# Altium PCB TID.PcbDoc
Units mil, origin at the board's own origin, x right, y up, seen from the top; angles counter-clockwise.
Board outline 3000 x 3000 mil, 2 copper layers (Top Layer, Bottom Layer), stack 60.8 mil thick; 40 components, 14 nets, 74 pads, 172 vias.
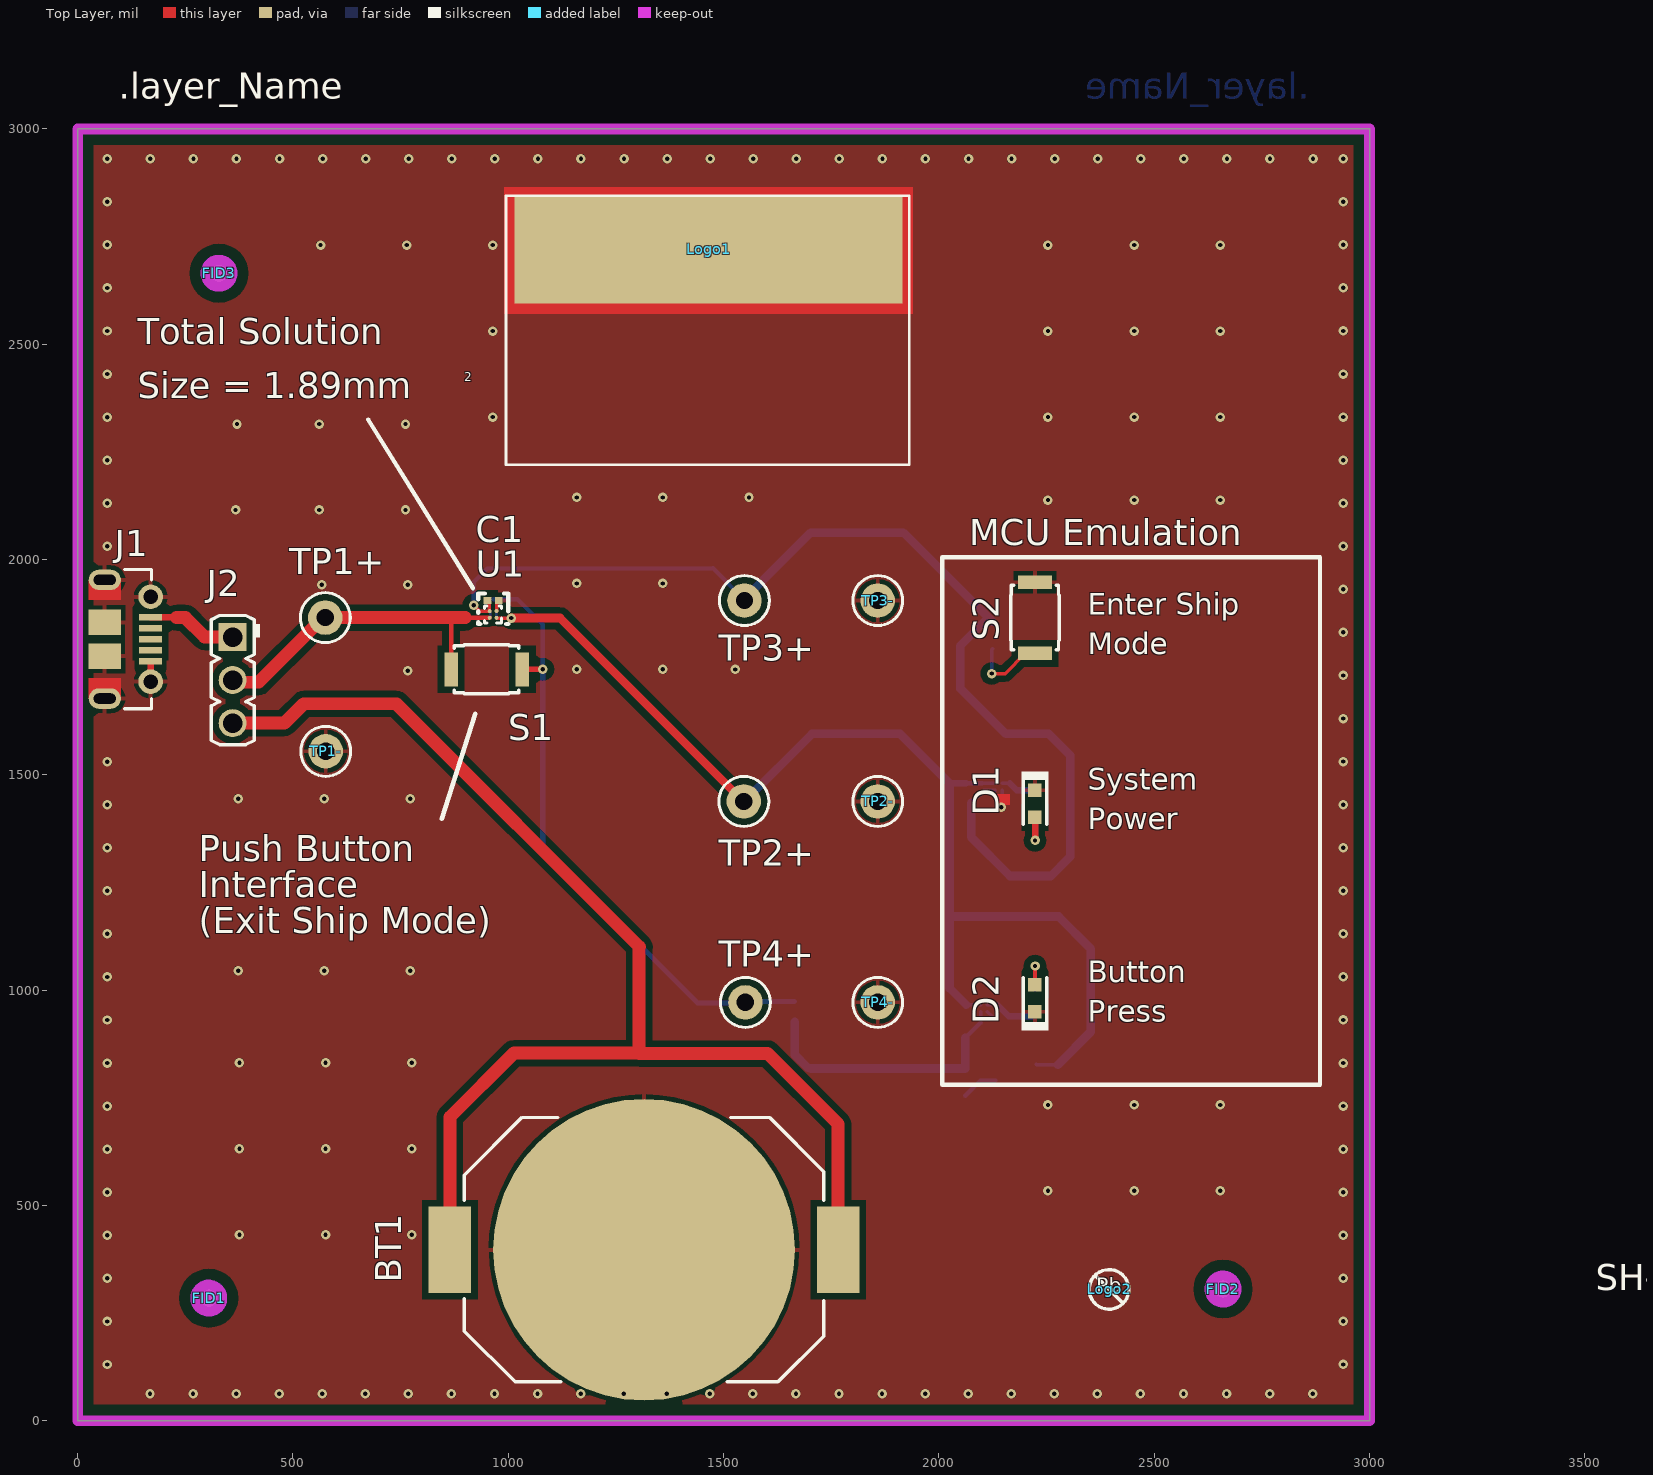
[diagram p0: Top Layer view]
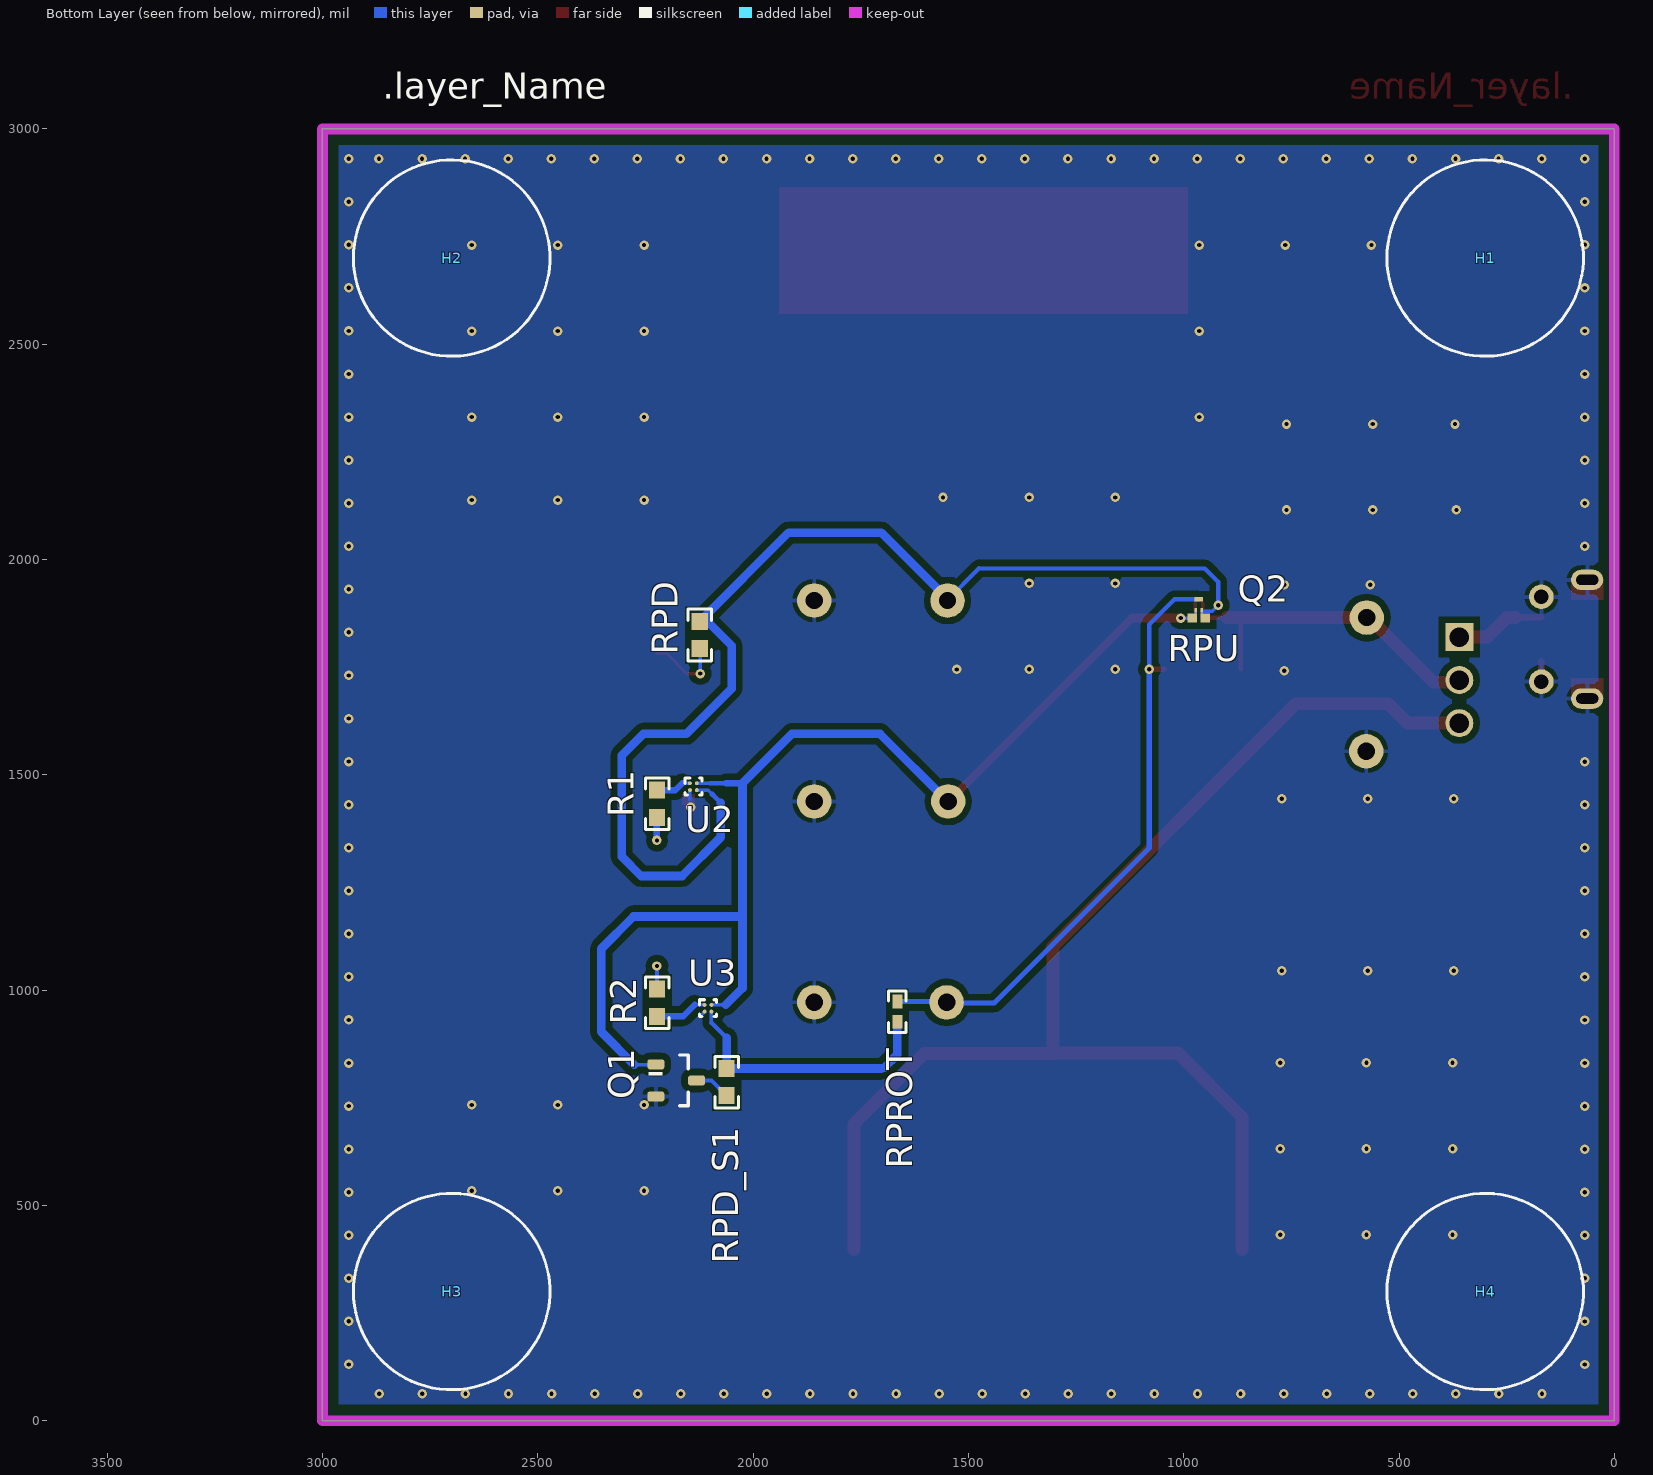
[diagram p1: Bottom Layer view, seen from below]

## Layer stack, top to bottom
Top Solder: solder mask 0.4, Solder Resist, Dk 3.5
Top Layer: signal copper 1.4
Dielectric1: core 58, FR-4, Dk 4.8
Bottom Layer: signal copper 1.4
Bottom Solder: solder mask 0.4, Solder Resist, Dk 3.5

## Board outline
0,0 3000,0 3000,3000 0,3000

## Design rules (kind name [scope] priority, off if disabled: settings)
AcuteAngle [All] p1: minimum=4.50000000000000E+0001 checktracksonly=FALSE
AssemblyTestPointUsage [All] p1: valid=2
Clearance Clearance_RPU2 [InComponent('RPU2')] p1: gap=5
Clearance "Clearance_J1 to Keep out" [HasFootprint('CONN_105017-0001') vs IsKeepOut] p2: gap=10
Clearance Clearance_track [IsTrack vs IsTrack] p3: gap=6
Clearance "Clearance_U1,U2 and U3" [InComponent('U*')] p4: gap=6
Clearance Clearance_Keepouts [((IsTrack Or IsArc) And Not InPoly) And IsFree and IsKeepOut vs ((IsTrack Or IsArc) And Not InPoly) And IsFree and IsKeepOut] p5: gap=0
Clearance Clearance_BoardEdge_MountingHoles [OnCopper and InComponentClass('Mounting Holes') vs IsKeepOut] p6: gap=25
Clearance Clearance_BoardEdge_Poly [OnCopper and InPoly vs IsKeepOut] p7: gap=25
Clearance Clearance_BoardEdge [OnCopper and Not InComponentClass('Logo') and not InComponentClass('FiducialMark') and not InRegion(1000,500,4000,800) and Not IsKeepout vs IsKeepOut] p8: gap=25
Clearance Clearance_Poly [InPolygon] p9: gap=15
Clearance [All] p10: gap=7.87
ComponentClearance ComponentClearance_MountingHoles_FiducialMarks [InComponentClass('Mounting Holes') vs InComponentClass('FiducialMark')] p1 off: gap=50 collisioncheckmode=3 verticalgap=10 showdistances=FALSE
ComponentClearance ComponentClearance_Shunt [InComponentClass('Header') vs InComponentClass('Shunt')] p2 off: gap=0 collisioncheckmode=3 verticalgap=0 showdistances=FALSE
ComponentClearance ComponentClearance_Logo [InComponentClass('Logo')] p3 off: gap=50 collisioncheckmode=3 verticalgap=10 showdistances=FALSE
ComponentClearance ComponentClearance_ScrewToNut [(HasFootprint('NY PMS 440 0025 PH')) vs (HasFootprint('Keystone_1902C'))] p4 off: gap=5 collisioncheckmode=3 verticalgap=10 showdistances=FALSE
ComponentClearance ComponentClearance_MountingHoles [InComponentClass('Mounting Holes')] p5 off: gap=250 collisioncheckmode=3 verticalgap=100000 showdistances=FALSE
ComponentClearance ComponentClearance_SmallPassives [HasFootprint('0201*') or HasFootprint('0402*') or HasFootprint('0508') or HasFootprint('0603*') or HasFootprint('0612') or HasFootprint('0805*') or HasFootprint('0815*') or HasFootprint('0830*') or HasFootprint('1206*') or HasFootprint('1210*') or HasFootprint('1808*') or HasFootprint('1812*') or HasFootprint('1825*') or HasFootprint('2010*') or HasFootprint('2220*') or HasFootprint('2225*') or HasFootprint('2512*') or HasFootprint('2728*') or HasFootprint('3518*') vs HasFootprint('0201*') or HasFootprint('0402*') or HasFootprint('0508') or HasFootprint('0603*') or HasFootprint('0612') or HasFootprint('0805*') or HasFootprint('0815*') or HasFootprint('0830*') or HasFootprint('1206*') or HasFootprint('1210*') or HasFootprint('1808*') or HasFootprint('1812*') or HasFootprint('1825*') or HasFootprint('2010*') or HasFootprint('2220*') or HasFootprint('2225*') or HasFootprint('2512*') or HasFootprint('2728*') or HasFootprint('3518*')] p6 off: gap=20 collisioncheckmode=3 verticalgap=10 showdistances=FALSE
ComponentClearance ComponentClearance_THtoSMT [IsThruComponent vs IsSMTComponent] p7 off: gap=100 collisioncheckmode=3 verticalgap=30 showdistances=FALSE
ComponentClearance ComponentClearance_THtoTH [IsThruComponent vs IsThruComponent] p8 off: gap=118.11 collisioncheckmode=3 verticalgap=30 showdistances=FALSE
ComponentClearance [All] p9 off: gap=40 collisioncheckmode=3 verticalgap=10 showdistances=FALSE
DiffPairsRouting [All] p1: maxlimit=100 minlimit=10 mostfreqgap=10 toplayer_minwidth=15 toplayer_maxwidth=15 toplayer_prefwidth=15 bottomlayer_minwidth=15 bottomlayer_maxwidth=15 bottomlayer_prefwidth=15 maxuncoupledlength=1000
FabricationTestPointUsage TestPointUsage [All] p1: valid=2 allowmultiple=FALSE
FabricationTestpoint Testpoint [All] p1: side=3 testpointundercomponent=TRUE minsize=40 maxsize=100 preferedsize=60 minholesize=0 maxholesize=40 preferedholesize=32 testpointgrid=1 allowsidetop=TRUE allowsidebottom=TRUE usegrid=TRUE gridtolerance=0.01
FanoutControl Fanout_LCC [IsLCC] p1: bgadir=Out bgaviamode=Centered fanoutstyle=Auto fanoutdirection=Alternating viagrid=1 // Fanout_LCC (Default Rule)
FanoutControl Fanout_BGA [IsBGA] p2: bgadir=Out bgaviamode=Centered fanoutstyle=Auto fanoutdirection=Alternating viagrid=1 // Fanout_BGA (Default Rule)
FanoutControl Fanout_Default [All] p4: bgadir=Out bgaviamode=Centered fanoutstyle=Auto fanoutdirection=Alternating viagrid=1 // Fanout_Default (Default Rule)
FanoutControl Fanout_Small [(CompPinCount < 5)] p5: bgadir=Out bgaviamode=Centered fanoutstyle=Auto fanoutdirection=OutThenIn viagrid=1 // Fanout_Small (Default Rule)
Height [All] p1 off: minheight=0 maxheight=1000 prefheight=500
HoleSize [All] p1: absolutevalues=TRUE maxlimit=251 minlimit=8 maxpercent=80.000 minpercent=20.000
MinimumAnnularRing MinimumAnnularRing_ThermalPadVias [IsVia and InAnyComponent] p1: minimumring=5.91
MinimumAnnularRing [All] p2: minimumring=6
MinimumSolderMaskSliver MinimumSolderMaskSliver_Logo [InComponentClass('Logo') vs InComponentClass('Logo')] p1: minsoldermaskwidth=0.7
MinimumSolderMaskSliver [All] p2: minsoldermaskwidth=3.94
PlaneClearance PlaneClearance_1 [All] p1: clearance=20
PlaneClearance [InNet('NetJ2_2')] p2: clearance=0
PlaneConnect [All] p1: planeconnectstyle=Relief reliefexpansion=10 reliefentries=4 reliefconductorwidth=10 reliefairgap=10
PolygonConnect [(InPadClass('All Pads'))] p1: connectstyle=Relief reliefconductorwidth=10 reliefentries=4 polygonreliefangle="90 Angle" airgapwidth=10
RoutingVias ThermalPadVias [IsVia and InAnyComponent] p1: holewidth=7.87 width=19.68 viastyle="Through Hole" minholewidth=7.87 minwidth=19.68 maxholewidth=12.99 maxwidth=23.62
RoutingVias [All] p2: holewidth=16 width=34 viastyle="Through Hole" minholewidth=7.87 minwidth=22 maxholewidth=40 maxwidth=65
SilkToBoardRegionClearance [Not ((IsComment or IsDesignator) And (Hide <> 'False')) and not InRegion(1000,500,4000,800)] p1:
SilkToSilkClearance SilkToSilkClearance_Pb-FreeLogo [(HasFootprint('Pb-Free_Overlay_Medium') OR HasFootprint('Pb-Free_Overlay_Small')) vs (HasFootprint('Pb-Free_Overlay_Medium') OR HasFootprint('Pb-Free_Overlay_Small'))] p1: silktosilkclearance=0
SilkToSilkClearance [All] p2: silktosilkclearance=5
SilkToSolderMaskClearance "Silk to Solder Mask Opening" [All] p1: minsilkscreentomaskgap=1 clearancetoexposedcopper=FALSE
SolderMaskExpansion [All] p1: expansion=1.97
UnpouredPolygon [All] p1: allowunpoured=FALSE
Width [All] p1: maxlimit=100 minlimit=6 preferedwidth=10 checkconnectedcopper=TRUE
12 further rules are at their usual default settings.

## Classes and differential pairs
component class Ship_Mode_Circuit: BT1 C1 D1 D2 J1 J2 Q1 Q2 R1 R2 RPD RPD_S1 RPROT RPU S1 S2 SH-J2 TP1+ TP1- TP2+ TP2- TP3+ TP3- TP4+ TP4- U1 U2 U3
component class Logo: Logo1
component class TID_Hardware: FID1 FID2 FID3 H1 H2 H3 H4 Logo1 Logo2 ZZ2 ZZ3 ZZ4
component class FiducialMark: FID1 FID2 FID3
component class AssemblyNote: ZZ2 ZZ3 ZZ4
component class Header: J2
component class Shunt: SH-J2

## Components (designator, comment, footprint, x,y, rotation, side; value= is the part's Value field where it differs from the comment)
BT1 "BAT-HLD-001" LINX_BAT-HLD-001 1315.3,397.2 r180 top
C1 "CL03A105MP3NSNC" 0201 965,1905 r0 top
D1 "Power Active" WL-SMCW_GREEN 2223.07,1432.7 r270 top
D2 "Button Active" WL-SMCW_GREEN 2223.07,981.2 r90 top
FID1 "Fiducial" Fiducial10-20 304.5,284.7 r0 top
FID2 "Fiducial" Fiducial10-20 2659.7,305.8 r0 top
FID3 "Fiducial" Fiducial10-20 328.2,2664.7 r0 top
H1 "SJ-5303 (CLEAR)" Bumpon_SJ5003Transparent 300,2700 r180 bottom
H2 "SJ-5303 (CLEAR)" Bumpon_SJ5003Transparent 2700,2700 r180 bottom
H3 "SJ-5303 (CLEAR)" Bumpon_SJ5003Transparent 2700,300 r180 bottom
H4 "SJ-5303 (CLEAR)" Bumpon_SJ5003Transparent 300,300 r180 bottom
J1 "105017-0001" CONN_105017-0001 116.2,1814.8 r270 top
J2 "61300311121" WURTH_61300311121 360,1720 r270 top
Logo1 "Texas Instruments" TI_Stacked_SolderMask_Small 1465,2720 r0 top
Logo2 "Pb-Free Symbol" Pb-Free_Overlay_Small 2395,305 r0 top
Q1 "BSS123" SOT-23 2178.56,790.2 r180 bottom
Q2 "CSD23382F4" YJC0003A 965,1895 r180 bottom
R1 "CRCW0603220RJNEA" 0603 2223.1,1432.7 r270 bottom
R2 "CRCW0603220RJNEA" 0603 2223.03,970.7 r90 bottom
RPD "CRCW0603100RJNEA" 0603 2123.96,1824.54 r90 bottom
RPD_S1 "RC1608J103CS" 0603 2061.36,786.4 r90 bottom
RPROT "CRCW04021K00JNED" 0402 1665,950 r270 bottom
RPU "RC0603F202CS" 0201M 965,1864 r0 bottom
S1 "Exit Ship Mode" SW_SKRKAEE010 950,1745 r180 top
S2 "Enter Ship Mode" SW_SKRKAEE010 2223.07,1864.54 r90 top
SH-J2 "969102-0000-DA" SNT-100-BK-G 3568,171 r90 top
TP1+ "5000" Keystone5000 575,1865 r90 top
TP1- "5001" Keystone5001 576.1,1554.6 r90 top
TP2+ "5000" Keystone5000 1546.9,1438.15 r90 top
TP2- "5001" Keystone5001 1858,1438.15 r90 top
TP3+ "5004" Keystone5004 1548.4,1904.7 r90 top
TP3- "5001" Keystone5001 1858,1904.7 r90 top
TP4+ "5004" Keystone5004 1550.5,971.6 r90 top
TP4- "5001" Keystone5001 1858,971.6 r90 top
U1 "TPS22915BYFP" YFP0004AAAA 964.7,1872.4 r180 top
U2 "TPS22915BYFP" YFP0004AAAA 2138.73,1472.4 r180 bottom
U3 "TPS22915BYFP" YFP0004AAAA 2104.7,957.9 r180 bottom
ZZ2 "These assemblies are ESD sensitive, ESD precautions shall be observed." AssemblyNote 5,3845 r0 top
ZZ3 "These assemblies must be clean and free from flux and all contaminants. Use of no clean flux is not acceptable." AssemblyNote 5,3577.5 r0 top
ZZ4 "These assemblies must comply with workmanship standards IPC-A-610 Class 2, unless otherwise specified." AssemblyNote 5,3310 r0 top

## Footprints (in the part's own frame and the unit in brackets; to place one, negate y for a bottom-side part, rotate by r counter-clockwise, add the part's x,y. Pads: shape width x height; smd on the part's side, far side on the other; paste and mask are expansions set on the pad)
0201 [mm] "Data from Kemet datasheet CC101_COM dated 7/28/11"
  rect 0.46x0.42 smd mask+0.048: 1(-0.33,0) 2(0.33,0)
  body extent -0.31,-0.16 0.31,0.16, height 0.26
0201M [mm] "Data from Kemet datasheet CC101_COM dated 7/28/11"
  rect 0.56x0.52 smd mask+0.048: 1(-0.38,0) 2(0.38,0)
  body extent -0.31,-0.16 0.31,0.16, height 0.26
0402 [mm] "0402 from SM-752 data"
  rect 0.8x0.6 smd: 1(-0.6,0) 2(0.6,0)
  silkscreen extent -1.22,-0.52 1.22,0.52, body extent -0.55,-0.3 0.55,0.3, height 0.6
0603 [mm] "0603 from SM-752 data"
  rect 1x0.95 smd: 1(-0.8,0) 2(0.8,0)
  silkscreen extent -1.52,-0.69 1.52,0.69, body extent -0.87,-0.47 0.87,0.47, height 0.85
AssemblyNote [mil] "Assembly Note"
Bumpon_SJ5003Transparent [mil] "3M Hemispherical Bumpon transparent"
  round 1 on Mech4: 0(0,0)
  silkscreen extent -228,-228 228,228, body extent -217,-218 219,218, height 197
CONN_105017-0001 [mm] "Molex Micro USB-B"
  rect 0.4x1.35 smd mask+0.051: 1(-1.3,1.35) 2(-0.65,1.35) 3(0,1.35) 4(0.65,1.35) 5(1.3,1.35)
  oval 1.2x1.9 hole 0.6 slot 1.3 at 90 deg: 6(-3.5,-1.35) 9(3.5,-1.35)
  rect 1.5x1.9 smd: 7(-1,-1.35) 8(1,-1.35)
  round 1.45 hole 0.85: 10(2.5,1.35) 11(-2.5,1.35)
  Top Layer region: 3.5,-0.4 2.3,-0.4 2.3,-2.3 3.5,-2.3
  Top Layer region: -3.5,-2.3 -2.3,-2.3 -2.3,-0.4 -3.5,-0.4
  silkscreen extent -4.1,-0.2 4.1,1.4, body extent -4.1,-3.93 4.1,1.5, height 2.72
Fiducial10-20 [mm]
  round 1 smd mask+0.5: 1(0,0)
  Top Layer keep-out circle w1.178: c0,0 r0.5
Keystone5000 [mil] "For Keystone 500x miniature loop terminals"
  round 80 hole 40: 1(0,0)
  silkscreen extent -58,-58 58,58, body extent -49,-49 49,49, height 182
Keystone5001 [mil] "For Keystone 500x miniature loop terminals"
  round 80 hole 40: 1(0,0)
  silkscreen extent -58,-58 58,58, body extent -49,-49 49,49, height 182
Keystone5004 [mil] "For Keystone 500x miniature loop terminals"
  round 80 hole 40: 1(0,0)
  silkscreen extent -58,-58 58,58, body extent -49,-49 49,49, height 182
LINX_BAT-HLD-001 [mm] "Linx Technologies"
  round 17.8 smd: 1(0,0)
  rect 2.5x5.1 smd: 2(-11.45,0) 3(11.45,0)
  silkscreen extent -10.6,-7.8 10.6,7.8, body extent -10.6,-7.8 10.6,7.8, height 4.31
Pb-Free_Overlay_Small [mil]
  silkscreen extent -46,-46 46,46
SNT-100-BK-G [mil] "Samtec STEP model"
  round 1 on Mech3: 0(0,0)
  body extent -100,-50 100,50, height 344
SOT-23 [mm] "SOT23, 3-Leads, Body 2.9x1.3mm, Pitch 0.95mm, Lead Span 2.5mm, IPC Medium Density"
  rrect50% 1x0.6 smd: 1(-1.2,0.95) 2(-1.2,-0.95) 3(1.2,0)
  silkscreen extent -1.63,-1.5 0.7,1.5, body extent -1.16,-1.45 1.21,1.45, height 1
SW_SKRKAEE010 [mm] "Alps recommended land pattern"
  rect 0.8x2 smd: 1(-2.1,0) 2(2.1,0)
  silkscreen extent -1.9,-1.44 1.92,1.44, body extent -2.4,-1.45 2.4,1.45, height 1.96
TI_Stacked_SolderMask_Small [mil]
  rect 900x250 smd paste-125 mask-125: 0(0,0)
WL-SMCW_GREEN [mm] "WURTH"
  rect 0.8x0.8 smd: 1(-0.8,0) 2(0.8,0)
  silkscreen extent -1.9,-0.8 1.2,0.8, body extent -0.85,-0.45 0.85,0.45, height 0.8
WURTH_61300311121 [mm] "Header, 2.54mm, 3x1, TH"
  rect 1.65x1.65 hole 1.15: 1(-2.54,0)
  round 1.65 hole 1.15: 2(0,0) 3(2.54,0)
  silkscreen extent -3.81,-1.27 3.81,1.6, body extent -3.81,-1.27 3.81,1.27, height 8.54
YFP0004AAAA [mm] "TI DSBGA 0.806x0.806mm"
  round 0.23 smd paste-0.13 mask+0: A1(-0.2,0.2) A2(0.2,0.2) B1(-0.2,-0.2) B2(0.2,-0.2)
  silkscreen extent -0.5,-0.5 0.5,0.5, body extent -0.39,-0.39 0.39,0.39, height 0.5
YJC0003A [mm] "TI"
  rect 0.16x0.26 smd: 1(-0.175,-0.325) 2(0.175,-0.325)
  rect 0.51x0.26 smd: 3(0,0.325)
  body extent -0.32,-0.52 0.32,0.52, height 0.35

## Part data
BT1: "Battery Holder, Retainer clip, SMT"
C1: "CAP, CERM, 1 µF, 10 V, +/- 20%, X5R, 0201"
D1 D2: library part 150060VS75000, "LED, Green, SMD"
FID1 FID2 FID3: "Fiducial mark.  There is nothing to buy or mount."
H1 H2 H3 H4: "Bumpon, Hemisphere, 0.44 X 0.20, Clear"
J1: "Connector, Receptacle, Micro-USB Type B, R/A, Bottom Mount SMT"
J2: "Header, 2.54 mm, 3x1, Gold, TH"
Logo1: library part TI_Logo, "Texas Instrument Corporate Signature"
Logo2: library part Pb-Free
Q1: "MOSFET, N-CH, 100 V, 0.17 A, SOT-23"
Q2: library part CSD23381F4, "MOSFET, P-CH, -12 V, -3.5 A,"
R1 R2: "RES, 220, 5%, 0.1 W, 0603"
RPD: "RES, 100, 5%, 0.1 W, 0603"
RPD_S1: "RES, 10 k, 5%, 0.1 W, 0603"
RPROT: "RES, 1.0 k, 5%, 0.063 W, 0402"
RPU: library part CRCW02011K80FKED, "RES, 2 k, 1%, 0.05 W, 0201"
S1 S2: library part SKRKAEE010, "Switch, Push Button, SMD"
SH-J2: "Shunt, 100mil, Gold plated, Black"
TP1+ TP2+: "Test Point, Miniature, Red, TH"
TP1- TP2- TP3- TP4-: "Test Point, Miniature, Black, TH"
TP3+ TP4+: "Test Point, Miniature, Yellow, TH"
U1 U2 U3: "Single Channel Ultra-Low Resistnace Load Switch, YFP0004AAAA"
ZZ2 ZZ3 ZZ4: library part AssemblyNote

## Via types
v1: diameter 22, hole 10, Top Layer to Bottom Layer, tented both sides, 172 vias

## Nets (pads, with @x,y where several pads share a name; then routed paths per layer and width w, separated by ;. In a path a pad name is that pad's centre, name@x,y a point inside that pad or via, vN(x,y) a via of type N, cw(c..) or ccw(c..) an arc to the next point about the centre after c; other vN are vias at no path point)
"BUTTON INDICATOR": RPD_S1.2 RPROT.2 U3.B2 | length 624.9
  Bottom Layer w8: 2096.83,924.23 U3.B2
  Bottom Layer w10: 2061.36,888.76 2096.83,924.23
  Bottom Layer w20: RPROT.2 1665,850 1695,820 ; 1702.11,817.89 RPD_S1.2 2061.36,888.76
DRAIN: Q2.3 RPROT.1 S1.1 TP4+.1 | length 1432
  Top Layer w12: S1.1@1045,1745 v1(1080,1745)
  Bottom Layer w10: Q2.3 1021.2,1907.8 1080,1849 v1(1080,1745)
  Bottom Layer w12: v1(1080,1745) 1080,1330 1440,970 TP4+.1@1555,970 ; TP4+.1@1550.5,973.62 RPROT.1
GATE: Q1.1 Q2.1 RPU.2 TP2+.1 U1.A1 U2.A2 U3.A2 | length 2763
  Top Layer w8: U1.A1@973,1865 974,1864 v1(1007,1864)
  Top Layer w20: v1(1007,1864) 1120,1864 TP2+.1@1546,1438
  Bottom Layer w6: RPU.2@971.89,1868.11 Q2.1
  Bottom Layer w8: RPU.2@981,1864 v1(1007,1864) ; 2063.1,966.4 2063.73,965.77 U3.A2 ; 2100.27,1480.27 U2.A2 ; Q1.1 2226.6,826.8 2276.4,826.8
  Bottom Layer w10: 2062.9,1480.27 2100.27,1480.27
  Bottom Layer w15: 2024.6,1478.57 2022.9,1480.27 2062.9,1480.27
  Bottom Layer w20: TP2+.1 1548.15,1438.15 1705,1595 1910,1595 2022.9,1482.1 2022.9,1480.27 ; 2024.6,1171 2277.8,1171 2352.7,1096.1 2352.7,903.1 2276.4,826.8 ; 2024.6,1478.57 2024.6,1004.9 2063.1,966.4
GND: BT1.1 C1.2 D1.1 D2.1 J1.5 J1.6 J1.7 J1.8 J1.9 J1.10 J1.11 Q1.2 S2.2 TP1-.1 TP2-.1 TP3-.1 TP4-.1 U1.B1 U2.B1 U3.B1 | length 101.7
  Top Layer w8: U1.B1 972.94,1880.64 C1.2@972.94,1897.94
  Top Layer w15: J1.10 J1.5
  Bottom Layer w8: U3.B1 2123.4,939.2 ; 2146.61,1443.19 U2.B1
  other v1: 168,62.4 268,62.4 368,62.4 468,62.4 568,62.4 668,62.4 768,62.4 868,62.4 968,62.4 1068,62.4 1168,62.4 1268,62.4 1368,62.4 1468,62.4 1568,62.4 1668,62.4 1768,62.4 1868,62.4 1968,62.4 2068,62.4 2168,62.4 2268,62.4 2368,62.4 2468,62.4 2568,62.4 2668,62.4 2768,62.4 2868,62.4 68.8,130.6 2939.2,130.7 68.8,230.6 2939.2,230.7 68.8,330.6 2939.2,330.7 68.8,430.6 2939.2,430.7 375.6,432.2 575.6,432.2 775.6,432.2 68.8,530.6 2939.2,530.7 2253.3,533.8 2453.3,533.8 2653.3,533.8 68.8,630.6 2939.2,630.7 375.6,631.8 575.6,631.8 775.6,631.8 68.8,730.6 2939.2,730.7 2253.3,733.4 2453.3,733.4 2653.3,733.4 68.8,830.6 2939.2,830.7 375.6,831.5 575.6,831.5 775.6,831.5 68.8,930.6 2939.2,930.7 68.8,1030.6 2939.2,1030.7 372.6,1045.1 572.6,1045.1 772.6,1045.1 68.8,1130.6 2939.2,1130.7 68.8,1230.6 2939.2,1230.7 68.8,1330.6 2939.2,1330.7 2145,1425 68.8,1430.6 2939.2,1430.7 372.6,1444.4 572.6,1444.4 772.6,1444.4 68.8,1530.6 2939.2,1530.7 2939.2,1630.7 2939.2,1730.7 766.6,1741.8 1159,1744.8 1359,1744.8 1527.1,1744.6 2939.2,1830.7 2939.2,1930.7 566.6,1941.4 766.6,1941.4 1159,1944.4 1359,1944.4 68.8,2030.6 2939.2,2030.7 366.6,2115 561.3,2115 761.3,2115 68.8,2130.6 2939.2,2130.7 2253.3,2138.1 2453.3,2138.1 2653.3,2138.1 1159,2144.1 1359,2144.1 1559,2144.1 68.8,2230.6 2939.2,2230.7 370,2314.6 561.3,2314.6 761.3,2314.6 68.8,2330.6 964,2330.8 2253.3,2330.8 2453.3,2330.8 2653.3,2330.8 2939.2,2330.7 68.8,2430.6 2939.2,2430.7 964,2530.4 2253.3,2530.4 2453.3,2530.4 2653.3,2530.4 68.8,2530.6 2939.2,2530.7 68.8,2630.6 2939.2,2630.7 564,2730.1 764,2730.1 964,2730.1 2253.3,2730.1 2453.3,2730.1 2653.3,2730.1 68.8,2730.6 2939.2,2730.7 68.8,2830.6 2939.2,2830.7 68.8,2930.6 168.8,2930.6 268.8,2930.6 368.8,2930.6 468.8,2930.6 568.8,2930.6 668.8,2930.6 768.8,2930.6 868.8,2930.6 968.8,2930.6 1068.8,2930.6 1168.8,2930.6 1268.8,2930.6 1368.8,2930.6 1468.8,2930.6 1568.8,2930.6 1668.8,2930.6 1768.8,2930.6 1868.8,2930.6 1968.8,2930.6 2068.8,2930.6 2168.8,2930.6 2268.8,2930.6 2368.8,2930.6 2468.8,2930.6 2568.8,2930.6 2668.8,2930.6 2768.8,2930.6 2868.8,2930.6 2939.2,2930.7
NetBT1_2: BT1.2 BT1.3 J2.3 | length 3076.9
  Top Layer w30: J2.3 480,1620 525,1665 740,1665 1303.7,1101.3 ; BT1.3 864.51,705.31 1012.8,853.6 1303.7,853.6 ; 1305,1100 1303.7,1101.3 ; BT1.2 1766.09,688.91 1602.3,852.7 1303.7,852.7 1303.7,853.6 ; 1303.7,853.6 1303.7,1101.3
NetD1_2: D1.2 R1.2 | length 107.6
  Top Layer w15: D1.2 2223.3,1400.97 v1(2223.3,1347.5)
  Bottom Layer w15: R1.2 2223.3,1401 v1(2223.3,1347.5)
NetD2_2: D2.2 R2.2 | length 97.3
  Top Layer w10: D2.2 2223.3,1012.93 v1(2223.3,1056)
  Bottom Layer w10: R2.2 2223.3,1002.46 v1(2223.3,1056)
NetJ1_1: J1.1 J2.1 | length 210.3
  Top Layer w15: J1.1 230.98,1865.98
  Top Layer w30: 230,1865 250,1865 295,1820 J2.1
NetJ2_2: J2.2 S1.2 TP1+.1 U1.A2 | length 778.6
  Top Layer w10: S1.2 867.32,1862.32 ; 900,1864 900.53,1864.53 U1.A2
  Top Layer w30: J2.2@360,1715 420,1715 TP1+.1@575,1870 ; TP1+.1 900,1865
NetQ1_3: Q1.3 RPD_S1.1 | length 84.6
  Bottom Layer w10: RPD_S1.1 2096.65,790.2 Q1.3
NetR1_1: R1.1 U2.A1 | length 83.2
  Bottom Layer w8: U2.A1 2164.73,1480.27
  Bottom Layer w15: 2164.73,1480.27 2180.8,1464.2 R1.1
NetR2_1: R2.1 U3.A1 | length 121.5
  Bottom Layer w8: U3.A1 2135.73,965.77
  Bottom Layer w15: 2135.73,965.77 2162.3,939.2 R2.1
NetRPD_1: RPD.1 S2.1 | length 178.5
  Top Layer w8: v1(2122.9,1735.1) 2154.2,1735.1 2200.96,1781.86 S2.1
  Bottom Layer w8: v1(2122.9,1735.1) 2122.9,1790.51 2124.7,1792.31 RPD.1
"SHIP MODE ENABLE": C1.1 Q2.2 RPD.2 RPU.1 TP3+.1 U1.B2 U2.B2 | length 2750.3
  Top Layer w8: v1(920,1894) 934,1880 U1.B2@957,1880 ; U1.B2@956.06,1881.04 C1.1@956.06,1898.94
  Bottom Layer w6: RPU.1@958.11,1871.11 Q2.2
  Bottom Layer w8: v1(920,1894) 934,1880 Q2.2@956.87,1880 ; 2095,1455 2104.53,1464.53 U2.B2
  Bottom Layer w10: v1(920,1894) 920,1948 951,1979 1475.35,1979.65 TP3+.1@1550,1905
  Bottom Layer w12: 2075,1435 2095,1455
  Bottom Layer w20: TP3+.1@1550,1910 1702.5,2062.5 1917.5,2062.5 RPD.2 2106.04,1856.04 2050,1800 2050,1700 2155,1595 2255,1595 2305,1545 2305,1310 2260,1265 2165,1265 2075,1355 2075,1435
pads on no net: FID1.1 FID2.1 FID3.1 H1.0 H2.0 H3.0 H4.0 J1.2 J1.3 J1.4 Logo1.0 SH-J2.0

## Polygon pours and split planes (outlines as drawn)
GND on Top Layer "Top Layer-No Net 3" (solid, remove dead copper, pour order 5): 0,0 0,3000 3000,3000 3000,0
GND on Bottom Layer "Top Layer-No Net 3" (solid, remove dead copper, pour order 4): 2.7,0 2.7,3000 3002.7,3000 3002.7,0

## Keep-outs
Keep-Out Layer:
  the board outline again, w25
  text ".Layer_Name" at 577,-858.49 h60

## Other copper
Top Layer:
  rectangle net GND: 990,2570 1940,2865
  rectangle net GND: 2135,1430 2165,1455
  text ".layer_Name" at 95,3070 h60
  text ".Layer_Name" at 577,-858.49 h60
Bottom Layer:
  text ".layer_Name" at 2860,3070 h60
  text ".Layer_Name" at 577,-858.49 h60

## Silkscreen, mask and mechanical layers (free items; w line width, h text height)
Top Overlay:
  lines w6: 994.7,2219.9 994.7,2299.6 994.7,2844.6 1926.5,2844.6 1931.6,2844.6 1931.6,2219.9 994.7,2219.9
  lines w10: 675,2325 918,1933 ; 845.6,1397.4 923.3,1641.9 ; 930,1854 930,1850 935,1850 ; 930,1876 930,1880 ; 930,1908 930,1921 945,1921 ; 990,1921 1000,1921 1000,1880 ; 995,1850 1000,1850 ; 2883.9,2005.2 2007.6,2005.2 2007.6,780 2885,780 2885,2005
  text ".layer_Name" at 95,3070 h60
  text "Total Solution" at 139,2500.2 h60
  text "2" at 898.2,2414.13 h20
  text "Size = 1.89mm" at 139,2374.15 h60
  text "MCU Emulation" at 2070.6,2033 h60
  text "Enter Ship" at 2345.7,1871.9 h50
  text "Mode" at 2345.7,1779.7 h50
  text "System" at 2345.7,1465.7 h50
  text "Power" at 2345.7,1373.5 h50
  text "Push Button" at 280.8,1298.7 h60
  text "Interface" at 280.8,1215.4 h60
  text "(Exit Ship Mode)" at 280.8,1132.5 h60
  text "Button" at 2345.7,1018.7 h50
  text "Press" at 2345.7,926.5 h50
  text ".Layer_Name" at 577,-858.49 h60
Bottom Overlay:
  text ".layer_Name" at 2860,3070 h60
  text ".Layer_Name" at 577,-858.49 h60
Top Paste:
  text ".Layer_Name" at 577,-858.49 h60
Bottom Paste:
  text ".Layer_Name" at 577,-858.49 h60
Top Solder:
  lines w10: 837.6,1665.3 837.9,1665.6 ; 918.9,1665.2 919,1665.3
  text ".layer_Name" at 95,3070 h60
  text ".PRJ_Number" at 1186.09,2521.5 h60
  text "Ship Mode" at 1216.2,2433.7 h60
  text "for Wearables" at 1101.12,2342.77 h60
  text "2015 TI" at 1286.06,2253.4 h60
  text "©" at 1182,2249.9 h105
  text ".Layer_Name" at 577,-858.49 h60
  text ".Layer_Name" at 577,-858.49 h60
Bottom Solder:
  text ".layer_Name" at 2860,3070 h60
  text ".Layer_Name" at 577,-858.49 h60
Drill Guide:
  text ".Layer_Name" at 577,-858.49 h60
M1 Board Outline:
  the board outline again, w10
  text ".Layer_Name" at 577,-858.49 h60
M2 Board Dimensions:
  rectangle: 0,-275 125,-150
  rectangle: 125,-400 500,-275
  lines w7: 0,-275 1000,-275 ; 125,-400 125,-150 ; 250,-400 250,-150 ; 500,-400 500,-150 ; 750,-400 750,-150 ; 0,-400 1000,-400 1000,-150 0,-150 0,-400
  text ".Layer_Name" at 577,-858.49 h60
M3 3D STEP Top:
  text ".Layer_Name" at 577,-858.49 h60
M4 3D STEP Bottom:
  text ".Layer_Name" at 577,-858.49 h60
M5 Assembly Top:
  lines w10: -292,-930.17 6308,-930.17 ; -292,-726.83 6310,-726.83 ; -292,-523.5 -292,-1133.5 3713,-1133.5 6310,-1133.5 6310,-523.5 -291.5,-523.5 -291.5,-1133.5 1284,-1133.5 ; 2173,-1133.5 2173,-523.5 ; 3440,-726.83 3440,-523.5 ; 4280,-726.83 4280,-523.5 ; 4902,-1140 4902,-937.17
  text "COMPONENTS MARKED 'DNP' SHOULD NOT BE POPULATED." at 1153.5,-318.5 h60
  text "ASSEMBLY VARIANT:" at 1153,-434 h60
  text ".VariantName" at 2189,-434 h60
  text "PCB VIEWED FROM TOP SIDE" at -228.5,-655.67 h60
  text "BOARD #:" at 2248,-655.67 h60
  text ".PRJ_Number" at 2793.5,-655.67 h60
  text "REV:" at 3638,-655.67 h60
  text ".PCB_Rev" at 3929.5,-655.67 h60
  text "SVN REV:" at 4476,-655.67 h60
  text ".VersionControl_RevNumber" at 4982,-655.67 h60
  text "TID #:" at 2248,-859 h60
  text ".TID" at 2793.5,-859 h60
  text "PLOT NAME =" at -228.5,-1064.34 h60
  text ".plot_File_Name" at 577,-1064.34 h60
  text "GENERATED    :" at 2250,-1064.34 h60
  text ".Print_Date" at 3119.5,-1064.34 h60
  text ".Print_Time" at 3848.5,-1064.34 h60
  text "TEXAS INSTRUMENTS" at 5113,-1064.34 h60
M6 Assembly Bottom:
  lines w10: -292.5,-727.33 6309.5,-727.33 ; -290.5,-930.67 6309.5,-930.67 ; 1115.5,-1140.5 1115.5,-937.67 ; 1737.5,-727.33 1737.5,-524 ; 2577.5,-727.33 2577.5,-524 ; 3844.5,-1134 3844.5,-524 ; 4733.5,-1134 6309,-1134 6309,-524 -292.5,-524 -292.5,-1134 2304.5,-1134 6309.5,-1134 6309.5,-524
  text "COMPONENTS MARKED 'DNP' SHOULD NOT BE POPULATED." at 6102,-318 h60
  text ".VariantName" at 5058,-434 h60
  text "ASSEMBLY VARIANT:" at 6097,-434 h60
  text ".VersionControl_RevNumber" at 1035.5,-656.17 h60
  text "SVN REV:" at 1541.5,-656.17 h60
  text ".PCB_Rev" at 2088,-656.17 h60
  text "REV:" at 2379.5,-656.17 h60
  text ".PRJ_Number" at 3224,-656.17 h60
  text "BOARD #:" at 3769.5,-656.17 h60
  text "PCB VIEWED FROM BOTTOM SIDE" at 6246,-656.17 h60
  text ".TID" at 3224,-859.5 h60
  text "TID #:" at 3769.5,-859.5 h60
  text "TEXAS INSTRUMENTS" at 904.5,-1064.84 h60
  text ".Print_Time" at 2169,-1064.84 h60
  text ".Print_Date" at 2898,-1064.84 h60
  text "GENERATED    :" at 3767.5,-1064.84 h60
  text ".plot_File_Name" at 5440.5,-1064.84 h60
  text "PLOT NAME =" at 6246,-1064.84 h60
M9 Title Sheet:
  drawing of 57 lines, arcs and shapes, not listed
  text "1" at 739.84,8036.5 h70
  text "2" at 3235.5,8036.5 h70
  text "3" at 5724.84,8036.5 h70
  text "4" at 8231.51,8036.5 h70
  text "5" at 10730.5,8036.5 h70
  text "6" at 13235.5,8036.5 h70
  text "A" at -416.5,6893.5 h70
  text "A" at 14383.5,6893.5 h70
  text "B" at -416.5,4513.5 h70
  text "B" at 14383.5,4513.5 h70
  text "C" at -416.5,2138.5 h70
  text "C" at 14383.5,2138.5 h70
  text "PROJECT TITLE:" at 11343.5,277.5 h45
  text ".PRJ_Title" at 11393.5,144.17 h70
  text "DESIGNED FOR:" at 11343.5,-23.5 h45
  text ".PRJ_Customer" at 11393.5,-163.5 h70
  text "D" at -416.5,-231.5 h70
  text "D" at 14383.5,-231.5 h70
  text "FILE NAME:" at 11343.5,-323.5 h45
  text ".PCB_File_Name_No_Path" at 11393.5,-443.5 h70
  text "Texas Instruments (TI) and/or its licensors do not warrant the accuracy or completeness of this specification" at 6374,-605.34 h45
  text "ENGINEER:" at 11343.5,-613.5 h45
  text "LAYOUT BY:" at 12848.5,-613.5 h45
  text "or any information contained therein. TI and/or its licensors do not warrant that this design will meet" at 6329.01,-718 h45
  text ".PRJ_Engineer" at 11393.5,-768.49 h70
  text ".PCB_Layout" at 12899,-768.49 h70
  text "the specifications, will be suitable for your application or fit for any particular purpose, or will operate in" at 6329.01,-830.67 h45
  text ".Layer_Name" at 577,-858.49 h60
  text "ALTIUM DESIGNER VERSION:" at 12848.5,-923.5 h45
  text "an implementation. TI and/or its licensors do not warrant that the design is production worthy. You should" at 6329.01,-943.33 h45
  text "completely validate and test your design implementation to confirm the system functionality for your application." at 6374,-1056 h45
  text ".print_Scale" at 11393.5,-1056.83 h70
  text ".Application_BuildNumber" at 12899,-1056.83 h70
  text "1" at 739.84,-1263.5 h70
  text "2" at 3235.5,-1263.5 h70
  text "3" at 5724.84,-1263.5 h70
  text "4" at 8231.51,-1263.5 h70
  text "5" at 10730.5,-1263.5 h70
  text "6" at 13235.5,-1263.5 h70
M10 Fab Notes:
  drawing of 185 lines, arcs and shapes, not listed
  text "DESIGN INFORMATION" at 12381.02,5910 h60
  text "MIN. TRACK WIDTH:" at 11736.46,5730 h60
  text "8" at 12832.7,5730 h60
  text "MIL" at 12987.46,5730 h60
  text "MIN. CLEARANCE:" at 11736.46,5598 h60
  text "0.2" at 12772.7,5598 h60
  text "mm" at 12987.46,5598 h60
  text "MIN. VIA PAD SIZE:" at 11736.46,5466 h60
  text "24" at 12802.71,5466 h60
  text "MIL" at 12987.46,5466 h60
  text "0.05mm (2MIL)" at 12431.46,5324.29 h60
  text "MINIMUM ANNULAR RING" at 11407.23,5320 h60
  text "EXTERNAL" at 13139.46,5320 h60
  text "PER" at 11607.23,5202 h60
  text "IPC-D-275 CLASS 2 LEVEL C" at 11827.23,5202 h60
  text "MIL, HOLES" at 13315.46,5089.71 h60
  text "+/-" at 12923,5089 h60
  text "+/-" at 13777,5089 h60
  text "REGISTRATION TOLERANCES:" at 11407.23,5084 h60
  text "METAL" at 12607,5084 h60
  text "5" at 13183.2,5084 h60
  text "3" at 14016.2,5084 h60
  text "MIL" at 14132.46,5084 h60
  text "MATERIAL:" at 11332.46,4874.54 h60
  text "FR-4 High Tg" at 12318.9,4734.21 h60
  text "FR-408" at 11753.46,4725.64 h60
  text "X" at 12165.46,4725.64 h60
  text "OTHER" at 13241.46,4725.64 h60
  text "62 MIL (1.6mm) +/-10%" at 12073.56,4562.92 h60
  text "THICKNESS:" at 11407.23,4558.64 h60
  text "X" at 11945.4,4558.64 h60
  text "OTHER" at 13358.46,4558.64 h60
  text "TOLERANCE:" at 11407.23,4400.64 h60
  text "X" at 12246.53,4400.64 h60
  text "ANSI IPC-6012 TYPE 3 CLASS 2" at 12433.48,4400.64 h60
  text "OTHER +/-" at 12433.46,4244.64 h60
  text "BOW & TWIST:" at 11407.23,4087.64 h60
  text "X" at 12246.53,4087.64 h60
  text "ANSI IPC-6012 TYPE 3 CLASS 2" at 12433.48,4087.64 h60
  text "OTHER +/-" at 12433.46,3929.13 h60
  text "DRILLING:" at 11332.46,3790.64 h60
  text "REFERENCE:" at 11407.23,3673.64 h60
  text "X" at 12055.46,3673.64 h60
  text "AS SHOWN" at 12242.46,3673.64 h60
  text "X" at 12956.46,3673.64 h60
  text "NC_DRILL FILES" at 13093.46,3673.64 h60
  text "PTH MIN COPPER THICKNESS:" at 11407.23,3515.64 h60
  text "X" at 12757.46,3515.64 h60
  text "1MIL" at 12894.46,3515.64 h60
  text "OTHER" at 13391.46,3515.64 h60
  text "BOARD FINISH:" at 11332.46,3356.64 h60
  text "SILKSCREEN:" at 11487.68,3238.64 h60
  text "X" at 12436.46,3238.64 h60
  text "TOP" at 12562.46,3238.64 h60
  text "X" at 12946.46,3238.64 h60
  text "BOTTOM" at 13073.46,3238.64 h60
  text "SILKSCREEN COLOR:" at 11487.68,3071.64 h60
  text "X" at 12435.42,3071.64 h60
  text "WHITE" at 12562.46,3071.64 h60
  text "OTHER" at 13073.46,3071.64 h60
  text "SOLDER RESIST COLOR:" at 11487.68,2901.64 h60
  text "X" at 12055.42,2742.44 h60
  text "GREEN" at 12182.46,2742.44 h60
  text "BLUE" at 12773.46,2742.44 h60
  text "OTHER" at 13311.46,2742.44 h60
  text "IMMERSION GOLD (ENIG)" at 12393.46,2553.92 h60
  text "ENEPIG" at 13731,2550.64 h60
  text "SURFACE FINISH:" at 11332.46,2549.64 h60
  text "X" at 12206.51,2549.64 h60
  text "IMM. TIN/SILVER OR EQUIV" at 11662,2392.64 h60
  text "OTHER" at 13093.46,2392.64 h60
  text "ARRAY/PANEL:" at 11332.46,2213.64 h60
  text "CUT AND TRIM PER MECH LAYER 1" at 12393.46,2209.35 h60
  text "N.C. ROUTE" at 12393.46,2057.64 h60
  text "X" at 13072.46,2057.64 h60
  text "V. SCORE" at 13259.46,2057.64 h60
  text "CERTIFICATION:" at 11332.46,1920.64 h60
  text "MATERIALS AND WORKMANSHIP FOR ALL PCBS" at 12057.46,1920.64 h60
  text "TO MEET OR EXCEED THE REQUIREMENTS OF:" at 12057.46,1822.64 h60
  text "X" at 11683.96,1686.13 h60
  text "ANSI IPC-A-600F CLASS ->" at 11822.96,1686.13 h60
  text "X" at 13462.02,1686.13 h60
  text "2" at 13580.96,1686.14 h60
  text "1" at 13265.96,1684.64 h60
  text "3" at 13934.96,1684.64 h60
  text "X" at 11686.02,1526.64 h60
  text "UL 94V-0" at 11822.96,1526.64 h60
  text "X" at 12498.02,1526.64 h60
  text "RoHS" at 12634.96,1526.64 h60
  text "OTHER" at 13279.36,1526.64 h60
  text "PER ORDER" at 13676.42,1526.64 h60
  text "ADDITIONAL REQUIREMENTS:" at 11332.46,1385.64 h60
  text "MICROSECTION:" at 11407.23,1270.64 h60
  text "YES" at 12312.96,1270.64 h60
  text "REQUIRED" at 13174.46,1114.49 h60
  text "BARE BOARD ELEC. TEST:" at 11407.23,1111.64 h60
  text "NONE" at 12712.96,1111.64 h60
  text "X" at 13047.46,1111.64 h60
  text "PER ORDER" at 13766.46,1111.64 h60
  text "MANUFACTURER'S UL:" at 11407.23,954.64 h60
  text "RAIL" at 12572.96,950.35 h60
  text "METAL" at 13064.77,950.35 h60
  text "X" at 13440,950 h60
  text "SILK" at 13576.46,950.35 h60
  text ".Layer_Name" at 577,-858.49 h60
M11 Gerber Information:
  lines w10: -292,-930.17 6308,-930.17 ; -292,-726.83 6310,-726.83 ; -292,-523.5 -292,-1133.5 3713,-1133.5 6310,-1133.5 6310,-523.5 -291.5,-523.5 -291.5,-1133.5 1284,-1133.5 ; 2173,-1133.5 2173,-523.5 ; 3440,-726.83 3440,-523.5 ; 4280,-726.83 4280,-523.5 ; 4902,-1140 4902,-937.17
  text "ALL ARTWORK VIEWED FROM TOP SIDE" at -228.5,-655.67 h60
  text "BOARD #:" at 2248,-655.67 h60
  text ".PRJ_Number" at 2793.5,-655.67 h60
  text "REV:" at 3638,-655.67 h60
  text ".PCB_Rev" at 3929.5,-655.67 h60
  text "SVN REV:" at 4476,-655.67 h60
  text ".VersionControl_RevNumber" at 4982,-655.67 h60
  text "LAYER NAME =" at -228.5,-858.49 h60
  text "TID #:" at 2248,-859 h60
  text ".TID" at 2793.5,-859 h60
  text "PLOT NAME =" at -228.5,-1064.34 h60
  text ".plot_File_Name" at 577,-1064.34 h60
  text "GENERATED    :" at 2250,-1064.34 h60
  text ".Print_Date" at 3119.5,-1064.34 h60
  text ".Print_Time" at 3848.5,-1064.34 h60
  text "TEXAS INSTRUMENTS" at 5113,-1064.34 h60
M12 Stackup:
  drawing of 191 lines, arcs and shapes, not listed
  text "Layer" at 9675.1,7565.6 h60
  text "Name" at 10085.01,7565.6 h60
  text "Material" at 11014.76,7565.6 h60
  text "Thickness" at 11874.52,7565.6 h60
  text "Constant" at 12524.36,7565.6 h60
  text "Board Layer Stack" at 13094.22,7565.6 h60
  text "1" at 9675.1,7445.6 h60
  text "Top Overlay" at 10085.01,7445.6 h60
  text "2" at 9675.1,7325.6 h60
  text "Top Solder" at 10085.01,7325.6 h60
  text "Solder Resist" at 11014.76,7325.6 h60
  text "0.40mil" at 11874.52,7325.6 h60
  text "3.5" at 12524.36,7325.6 h60
  text "3" at 9675.1,7205.6 h60
  text "Top Layer" at 10085.01,7205.6 h60
  text "Copper" at 11014.76,7205.6 h60
  text "1.40mil" at 11874.52,7205.6 h60
  text "4" at 9675.1,7085.6 h60
  text "Dielectric1" at 10085.01,7085.6 h60
  text "FR-4" at 11014.76,7085.6 h60
  text "58.00mil" at 11874.52,7085.6 h60
  text "4.8" at 12524.36,7085.6 h60
  text "5" at 9675.1,6965.6 h60
  text "Bottom Layer" at 10085.01,6965.6 h60
  text "Copper" at 11014.76,6965.6 h60
  text "1.40mil" at 11874.52,6965.6 h60
  text "6" at 9675.1,6845.6 h60
  text "Bottom Solder" at 10085.01,6845.6 h60
  text "Solder Resist" at 11014.76,6845.6 h60
  text "0.40mil" at 11874.52,6845.6 h60
  text "3.5" at 12524.36,6845.6 h60
  text "7" at 9675.1,6725.6 h60
  text "Bottom Overlay" at 10085.01,6725.6 h60
  text ".Layer_Name" at 577,-858.49 h60
M13 Component Bodies Top:
  text ".Layer_Name" at 577,-858.49 h60
M14 Component Bodies Bottom:
  text ".Layer_Name" at 577,-858.49 h60
M15 Courtyards Top:
  text ".Layer_Name" at 577,-858.49 h60
M16 Courtyards Bottom:
  text ".Layer_Name" at 577,-858.49 h60
Drill Drawing:
  circle w1: c3698.2,2129.47 r24.91
  lines w1: 3673.29,1668.64 3685.75,1668.64 3698.2,1656.19 3710.66,1668.64 3723.11,1668.64 3710.66,1681.1 3723.11,1693.55 3710.66,1693.55 3698.2,1706.01 3685.75,1693.55 3673.29,1693.55 3685.75,1681.1 3673.29,1668.64 ; 3673.29,1805.64 3723.11,1805.64 3723.11,1855.46 3673.29,1855.46 3673.29,1805.64 ; 3673.29,2004.92 3723.11,2004.92 3698.2,1955.1 3673.29,2004.92 ; 3673.29,2254.02 3698.2,2266.48 3723.11,2254.02 3710.66,2278.93 3723.11,2303.84 3698.2,2291.38 3673.29,2303.84 3685.75,2278.93 3673.29,2254.02
  lines w12: 3605.4,1611.35 5724.8,1611.35 ; 3605.4,2358.64 5724.8,2358.64 ; 3976.07,1461.89 3976.07,2508.1 ; 4333.18,1461.89 4333.18,2508.1 ; 4995.19,1461.89 4995.19,2508.1 ; 5279.54,1461.89 5279.54,2508.1 ; 3605.4,1461.89 5724.8,1461.89 5724.8,2508.1 3605.4,2508.1 3605.4,1461.89
  text "Symbol" at 3695.08,2403.48 h72
  text "Quantity" at 4020.91,2403.48 h72
  text "Finished Hole Size" at 4378.02,2403.48 h72
  text "Plated" at 5040.02,2403.48 h72
  text "Hole Type" at 5324.38,2403.48 h72
  text "172" at 4020.91,2254.02 h60
  text "10.00mil (0.254mm)" at 4378.02,2254.02 h60
  text "PTH" at 5040.02,2254.02 h60
  text "Round" at 5324.38,2254.02 h60
  text "2" at 4020.91,2104.56 h60
  text "33.46mil (0.850mm)" at 4378.02,2104.56 h60
  text "PTH" at 5040.02,2104.56 h60
  text "Round" at 5324.38,2104.56 h60
  text "8" at 4020.91,1955.1 h60
  text "40.00mil (1.016mm)" at 4378.02,1955.1 h60
  text "PTH" at 5040.02,1955.1 h60
  text "Round" at 5324.38,1955.1 h60
  text "3" at 4020.91,1805.64 h60
  text "45.28mil (1.150mm)" at 4378.02,1805.64 h60
  text "PTH" at 5040.02,1805.64 h60
  text "Round" at 5324.38,1805.64 h60
  text "2" at 4020.91,1656.19 h60
  text "23.62mil (0.600mm)" at 4378.02,1656.19 h60
  text "PTH" at 5040.02,1656.19 h60
  text "Slot" at 5324.38,1656.19 h60
  text "187 Total" at 4020.91,1506.73 h60
  text ".Layer_Name" at 577,-858.49 h60

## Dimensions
0,-400 to 1000,-400 on M2 Board Dimensions
0,0 to 0,3000 on M2 Board Dimensions
0,0 to 3000,0 on M2 Board Dimensions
